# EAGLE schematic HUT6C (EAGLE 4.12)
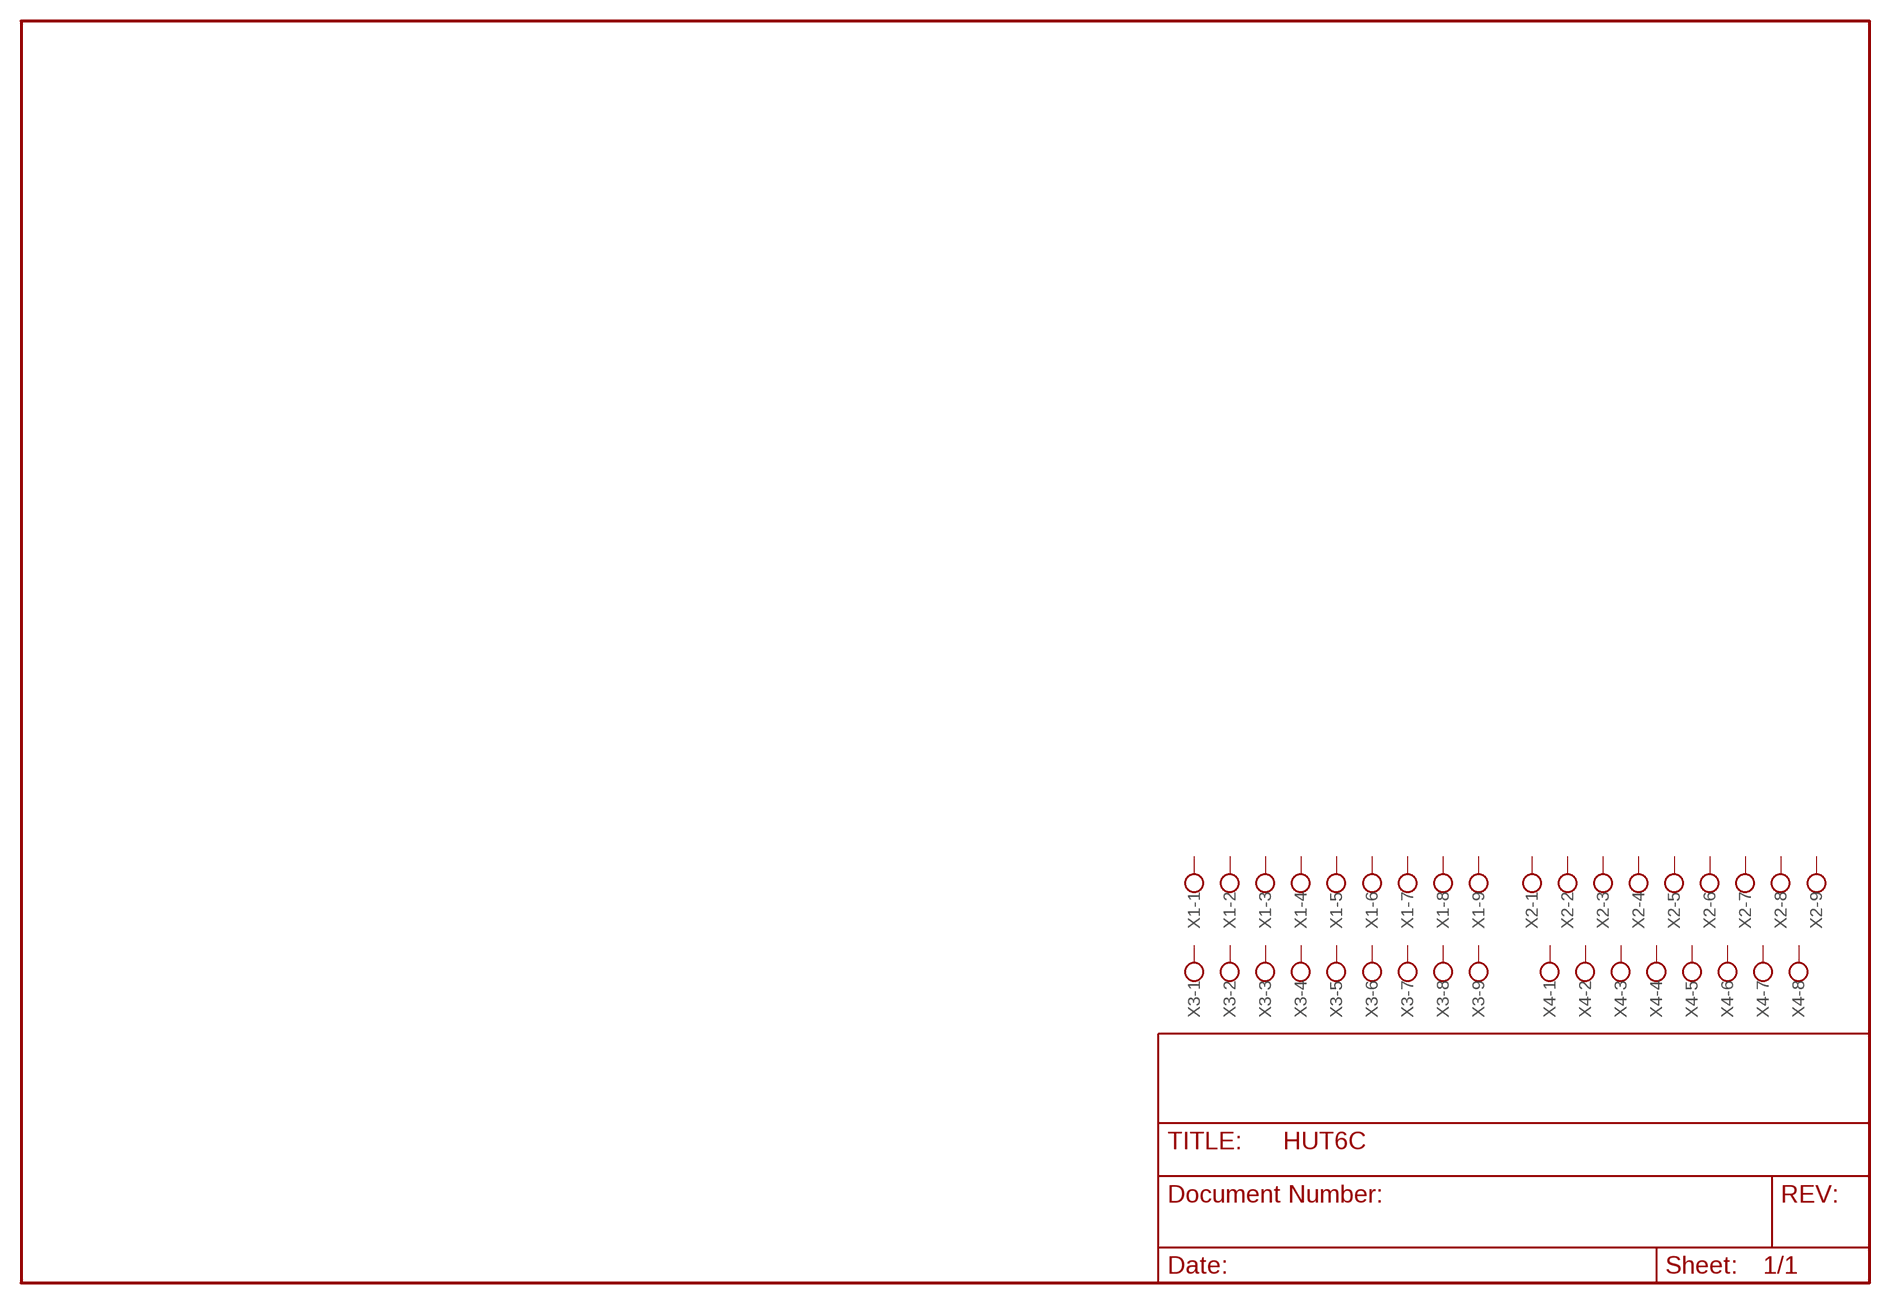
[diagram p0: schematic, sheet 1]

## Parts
X1  W237-09P  [W237-9P]
X2  W237-09P  [W237-9P]
X3  W237-09P  [W237-9P]
X4  W237-08P  [W237-8P]
Unconnected: X1.1 X1.2 X1.3 X1.4 X1.5 X1.6 X1.7 X1.8 X1.9 X2.1 X2.2 X2.3 X2.4 X2.5 X2.6 X2.7 X2.8 X2.9 X3.1 X3.2 X3.3 X3.4 X3.5 X3.6 X3.7 X3.8 X3.9 X4.1 X4.2 X4.3 X4.4 X4.5 X4.6 X4.7 X4.8

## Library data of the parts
X1-X3 = con-wago-508:W237-09P: WAGO SREW CLAMP
X4 = con-wago-508:W237-08P: WAGO SREW CLAMP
